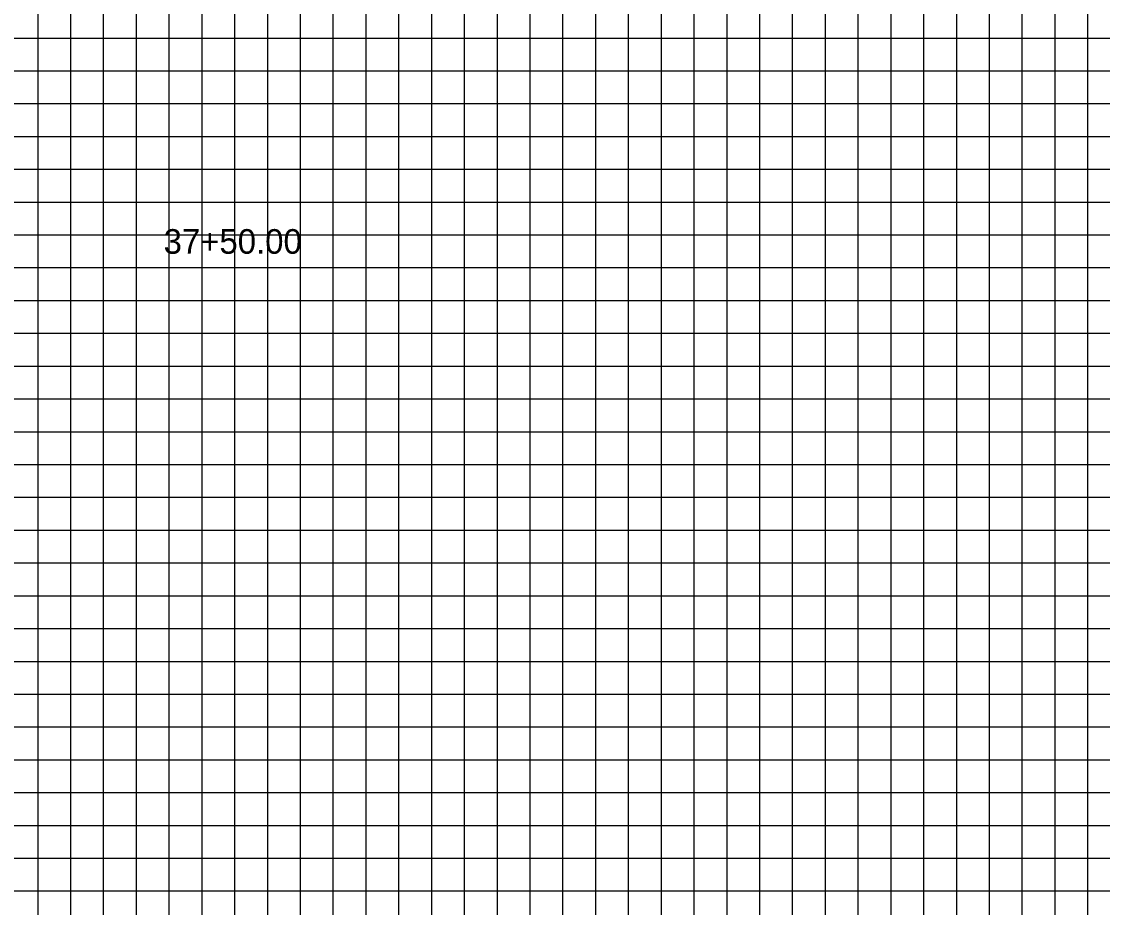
# Model space of a CAD drawing. Extents: x 967 to 1326, y 964 to 2024.
# Drawn here: x 1147 to 1212.9, y 1299 to 1353 of the extents above; entities that cross this region are included whole.
import ezdxf

# ---------------------------------------------------------------- set-up
doc = ezdxf.new("R2010")
doc.units = 0
for name, color, linetype in [('Default', 7, 'Continuous'), ('RD_SHT_MjGrid', 7, 'Continuous'), ('RD_SHT_MnGrid', 7, 'Continuous')]:
    doc.layers.add(name, color=color, linetype=linetype)

msp = doc.modelspace()

# ---------------------------------------------------------------- linework, layer by layer
at = {"layer": 'RD_SHT_MjGrid'}
for p, q in [((1150, 1280), (1150, 1450)), ((1160, 1280), (1160, 1450)), ((1170, 1280), (1170, 1450)), ((1180, 1280), (1180, 1450)), ((1190, 1280), (1190, 1450)), ((1200, 1280), (1200, 1450)), ((1210, 1280), (1210, 1450)), ((1000, 1350), (1320, 1350)), ((1000, 1340), (1320, 1340)), ((1000, 1330), (1320, 1330)), ((1000, 1320), (1320, 1320)), ((1000, 1310), (1320, 1310)), ((1000, 1300), (1320, 1300))]:
    msp.add_line(p, q, dxfattribs=at)
at = {"layer": 'RD_SHT_MnGrid'}
for p, q in [((1148, 1280), (1148, 1450)), ((1152, 1280), (1152, 1450)), ((1154, 1280), (1154, 1450)), ((1156, 1280), (1156, 1450)), ((1158, 1280), (1158, 1450)), ((1162, 1280), (1162, 1450)), ((1164, 1280), (1164, 1450)), ((1166, 1280), (1166, 1450)), ((1168, 1280), (1168, 1450)), ((1172, 1280), (1172, 1450)), ((1174, 1280), (1174, 1450)), ((1176, 1280), (1176, 1450)), ((1178, 1280), (1178, 1450)), ((1182, 1280), (1182, 1450)), ((1184, 1280), (1184, 1450)), ((1186, 1280), (1186, 1450)), ((1188, 1280), (1188, 1450)), ((1192, 1280), (1192, 1450)), ((1194, 1280), (1194, 1450)), ((1196, 1280), (1196, 1450)), ((1198, 1280), (1198, 1450)), ((1202, 1280), (1202, 1450)), ((1204, 1280), (1204, 1450)), ((1206, 1280), (1206, 1450)), ((1208, 1280), (1208, 1450)), ((1212, 1280), (1212, 1450)), ((1000, 1352), (1320, 1352)), ((1000, 1348), (1320, 1348)), ((1000, 1346), (1320, 1346)), ((1000, 1344), (1320, 1344)), ((1000, 1342), (1320, 1342)), ((1000, 1338), (1320, 1338)), ((1000, 1336), (1320, 1336)), ((1000, 1334), (1320, 1334)), ((1000, 1332), (1320, 1332)), ((1000, 1328), (1320, 1328)), ((1000, 1326), (1320, 1326)), ((1000, 1324), (1320, 1324)), ((1000, 1322), (1320, 1322)), ((1000, 1318), (1320, 1318)), ((1000, 1316), (1320, 1316)), ((1000, 1314), (1320, 1314)), ((1000, 1312), (1320, 1312)), ((1000, 1308), (1320, 1308)), ((1000, 1306), (1320, 1306)), ((1000, 1304), (1320, 1304)), ((1000, 1302), (1320, 1302))]:
    msp.add_line(p, q, dxfattribs=at)

# ---------------------------------------------------------------- texts
at = {"layer": 'Default'}
msp.add_text('37+50.00', height=1.5, dxfattribs=at).set_placement((1155.656, 1338.848))

doc.saveas('drawing.dxf')
